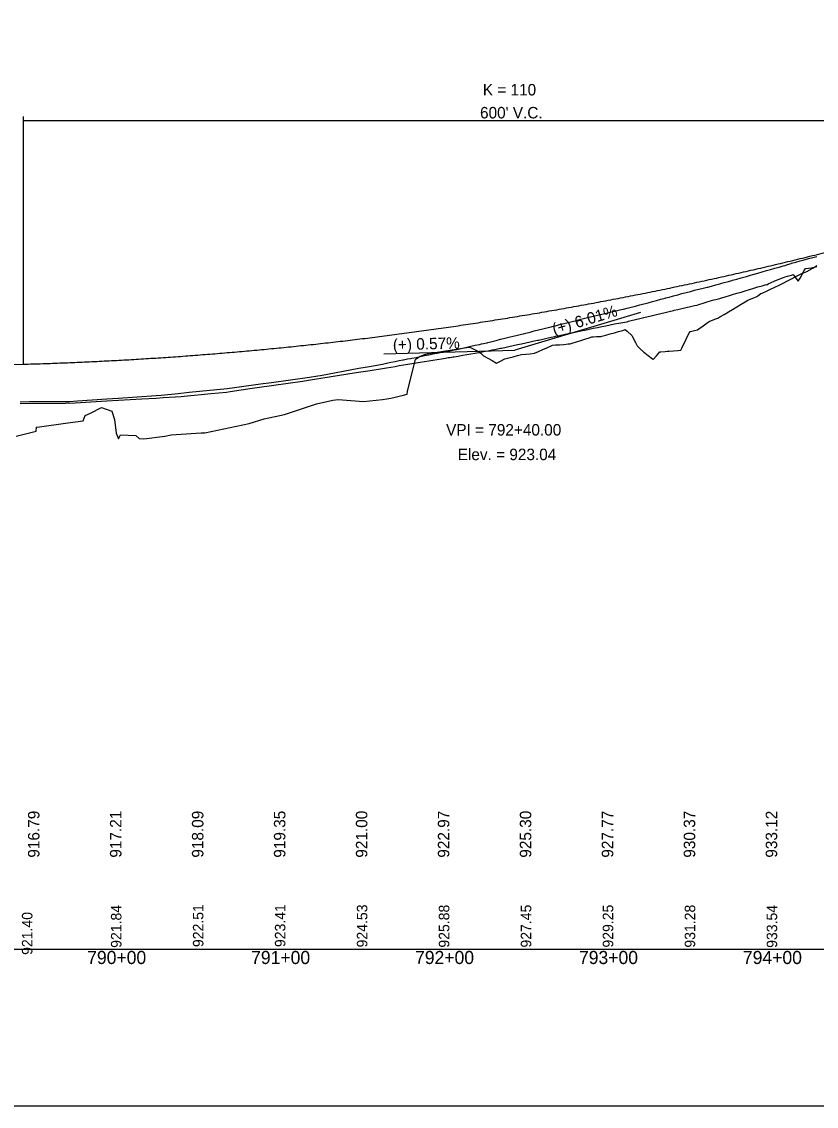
# Model space of a CAD drawing. Extents: x 1558113 to 1562835, y 1129435 to 1135883.
# Drawn here: x 1560436 to 1560920, y 1133348 to 1134009 of the extents above; entities that cross this region are included whole.
import ezdxf

# ---------------------------------------------------------------- set-up
doc = ezdxf.new("R2010")
doc.units = 0
for name, color, linetype in [('BR_EXIST_GROUND_LT', 7, 'Continuous'), ('BR_EXIST_GROUND_RT', 7, 'Continuous'), ('RD_DDB_GradeTX', 7, 'Continuous'), ('RD_DDB_Profile_EX', 7, 'Continuous'), ('RD_DDB_Profile_Lbl', 7, 'Continuous'), ('RD_DDB_Profile_PR', 7, 'Continuous'), ('RD_DDB_StaTX', 7, 'Continuous'), ('RD_DDB_StripGrade', 7, 'Continuous'), ('RD_DDB_VCLbl', 7, 'Continuous'), ('RD_GPK_Profile_Cell', 7, 'Continuous'), ('RD_SHT_ShtClip', 7, 'Continuous')]:
    doc.layers.add(name, color=color, linetype=linetype)

msp = doc.modelspace()

# ---------------------------------------------------------------- linework, layer by layer
at = {"layer": 'BR_EXIST_GROUND_LT'}
msp.add_lwpolyline([(1560432.22, 1133756.64), (1560444.39, 1133759.72), (1560444.6, 1133762.19), (1560444.93, 1133762.16), (1560463.73, 1133764.8), (1560473.02, 1133765.97), (1560474.21, 1133769.22), (1560477.53, 1133770.62), (1560484.26, 1133774.04), (1560490.55, 1133771.91), (1560492.06, 1133766.88), (1560493.06, 1133758.51), (1560494.52, 1133754.99), (1560495.76, 1133757.46), (1560505.12, 1133757.14), (1560507.15, 1133755.18), (1560510.04, 1133755.02), (1560522.83, 1133756.74), (1560526.72, 1133757.57), (1560545.07, 1133758.64), (1560545.49, 1133758.7), (1560547.25, 1133758.76), (1560574.36, 1133764.45), (1560583.49, 1133767.31), (1560595.83, 1133769.83), (1560615.41, 1133776.42), (1560625.36, 1133778.7), (1560628.57, 1133779.09), (1560644.1, 1133777.88), (1560655.52, 1133779.07), (1560658.33, 1133779.39), (1560660.67, 1133779.87), (1560663.24, 1133780.44), (1560665.82, 1133781.05), (1560668.39, 1133781.7), (1560670.57, 1133782.3), (1560670.96, 1133783.91), (1560673.54, 1133794.59), (1560675.65, 1133803.39), (1560676.11, 1133803.72), (1560678.69, 1133805.48), (1560679.45, 1133805.72), (1560681.26, 1133806.35), (1560682.79, 1133806.88), (1560683.83, 1133807.07), (1560686.41, 1133807.48), (1560688.98, 1133807.89), (1560691.56, 1133808.29), (1560694.13, 1133808.7), (1560696.7, 1133809.1), (1560699.28, 1133809.51), (1560701.85, 1133809.91), (1560704.43, 1133810.32), (1560707, 1133810.73), (1560708.75, 1133811), (1560709.62, 1133810.59), (1560712.15, 1133809.33), (1560714.67, 1133808.08), (1560715.45, 1133807.48), (1560717.3, 1133805.72), (1560719.87, 1133804.25), (1560722.45, 1133802.78), (1560725.23, 1133801.22), (1560727.59, 1133802.45), (1560730.17, 1133803.79), (1560732.74, 1133804.45), (1560735.32, 1133805.11), (1560737.89, 1133805.79), (1560740.46, 1133806.44), (1560743.04, 1133806.69), (1560745.61, 1133806.95), (1560748.24, 1133807.22), (1560750.76, 1133808.31), (1560753.33, 1133809.43), (1560755.91, 1133810.57), (1560758.48, 1133811.71), (1560759.39, 1133812.12), (1560761.06, 1133812.24), (1560763.63, 1133812.44), (1560766.2, 1133812.64), (1560768.78, 1133812.87), (1560770.13, 1133812.99), (1560771.35, 1133813.35), (1560773.93, 1133814.14), (1560776.5, 1133814.94), (1560779.07, 1133815.75), (1560781.65, 1133816.58), (1560783.32, 1133817.12), (1560784.22, 1133817.23), (1560786.22, 1133817.47), (1560786.8, 1133817.46), (1560788.7, 1133817.43), (1560789.37, 1133817.61), (1560791.94, 1133818.29), (1560794.52, 1133818.99), (1560797.09, 1133819.7), (1560799.67, 1133820.44), (1560802.24, 1133821.18), (1560803.72, 1133821.62), (1560804.81, 1133820.63), (1560807.64, 1133818.12), (1560809.96, 1133813.7), (1560811.02, 1133811.7), (1560812.54, 1133810.02), (1560815.11, 1133807.9), (1560817.68, 1133805.81), (1560820.26, 1133803.75), (1560820.79, 1133803.34), (1560822.83, 1133805.73), (1560824.77, 1133808.04), (1560825.41, 1133808.08), (1560827.98, 1133808.29), (1560829.28, 1133808.41), (1560830.55, 1133808.48), (1560833.13, 1133808.65), (1560835.7, 1133808.85), (1560837.61, 1133809.03), (1560838.28, 1133810.4), (1560840.85, 1133815.72), (1560843.08, 1133820.37), (1560843.42, 1133820.44), (1560846, 1133821.05), (1560847.81, 1133821.49), (1560848.57, 1133822.03), (1560851.15, 1133823.89), (1560853.72, 1133825.77), (1560854.83, 1133826.58), (1560856.3, 1133827.14), (1560858.87, 1133828.14), (1560860.1, 1133828.62), (1560861.44, 1133829.39), (1560864.02, 1133830.88), (1560866.59, 1133832.39), (1560869.17, 1133833.92), (1560871.74, 1133835.47), (1560874.31, 1133837.04), (1560876.89, 1133838.64), (1560878.5, 1133839.65), (1560879.46, 1133840.02), (1560882.04, 1133841.03), (1560883.87, 1133841.78), (1560884.61, 1133842.28), (1560886.49, 1133843.57), (1560887.18, 1133843.89), (1560889.76, 1133845.07), (1560892.33, 1133846.28), (1560894.91, 1133847.51), (1560897.48, 1133848.76), (1560900.05, 1133850.03), (1560902.63, 1133851.33), (1560905.2, 1133852.65), (1560907.78, 1133853.99), (1560910.61, 1133855.49), (1560912.92, 1133856.46), (1560915.02, 1133857.35), (1560915.5, 1133857.62), (1560918.07, 1133859.11), (1560920.65, 1133860.63)], dxfattribs=at)
at = {"layer": 'BR_EXIST_GROUND_RT'}
msp.add_lwpolyline([(1560434.56, 1133776.53), (1560462.28, 1133776.75), (1560463.96, 1133776.88), (1560464.87, 1133776.85), (1560487.39, 1133778.29), (1560508.75, 1133779.37), (1560517.64, 1133779.81), (1560521.77, 1133780.2), (1560532.83, 1133780.77), (1560534.58, 1133781), (1560551.06, 1133782.57), (1560560.38, 1133783.54), (1560562.72, 1133783.9), (1560576.19, 1133785.83), (1560586.52, 1133787.38), (1560589.32, 1133787.77), (1560606.82, 1133790.27), (1560611.65, 1133791.1), (1560615.42, 1133791.69), (1560618.05, 1133792.07), (1560639.5, 1133795.38), (1560648.01, 1133796.64), (1560655.52, 1133797.94), (1560658.09, 1133798.37), (1560660.67, 1133798.8), (1560663.24, 1133799.23), (1560665.82, 1133799.66), (1560668.39, 1133800.09), (1560671.15, 1133800.55), (1560673.54, 1133800.93), (1560676.11, 1133801.35), (1560678.69, 1133801.77), (1560681.26, 1133802.19), (1560683.83, 1133802.61), (1560686.41, 1133803.03), (1560688.98, 1133803.44), (1560691.56, 1133803.85), (1560694.13, 1133804.26), (1560695.76, 1133804.52), (1560696.7, 1133804.66), (1560698.8, 1133804.98), (1560699.28, 1133805.06), (1560701.85, 1133805.5), (1560704.43, 1133805.94), (1560707, 1133806.38), (1560709.58, 1133806.82), (1560712.15, 1133807.25), (1560713.09, 1133807.4), (1560714.72, 1133807.73), (1560717.3, 1133808.23), (1560719.87, 1133808.73), (1560722.45, 1133809.23), (1560723, 1133809.34), (1560725.02, 1133809.74), (1560727.59, 1133810.25), (1560728.2, 1133810.37), (1560730.17, 1133810.8), (1560732.74, 1133811.37), (1560735.32, 1133811.93), (1560737.89, 1133812.49), (1560740.46, 1133813.04), (1560743.04, 1133813.59), (1560745.61, 1133814.14), (1560746.48, 1133814.32), (1560748.19, 1133814.69), (1560750.29, 1133815.14), (1560750.76, 1133815.25), (1560753.33, 1133815.83), (1560755.91, 1133816.4), (1560758.48, 1133816.97), (1560760.7, 1133817.46), (1560761.06, 1133817.53), (1560763.63, 1133818.09), (1560766.2, 1133818.65), (1560768.78, 1133819.2), (1560771.35, 1133819.75), (1560773.93, 1133820.29), (1560776.5, 1133820.83), (1560777.57, 1133821.05), (1560779.07, 1133821.37), (1560781.65, 1133821.91), (1560784.22, 1133822.44), (1560786.8, 1133822.97), (1560789.37, 1133823.5), (1560791.94, 1133824.02), (1560794.52, 1133824.54), (1560797.09, 1133825.06), (1560799.76, 1133825.59), (1560802.24, 1133825.94), (1560803.49, 1133826.11), (1560804.81, 1133826.46), (1560805.62, 1133826.67), (1560807.39, 1133827.11), (1560809.96, 1133827.76), (1560812.54, 1133828.4), (1560815.11, 1133829.03), (1560817.68, 1133829.66), (1560820.26, 1133830.28), (1560822.83, 1133830.9), (1560825.47, 1133831.52), (1560827.98, 1133832.13), (1560830.55, 1133832.74), (1560833.13, 1133833.35), (1560833.57, 1133833.45), (1560835.7, 1133833.94), (1560838.28, 1133834.53), (1560840.85, 1133835.11), (1560843.42, 1133835.68), (1560846, 1133836.25), (1560847.66, 1133836.61), (1560848.57, 1133836.9), (1560851.15, 1133837.69), (1560853.72, 1133838.48), (1560856.3, 1133839.27), (1560857.77, 1133839.72), (1560858.87, 1133840), (1560861.44, 1133840.66), (1560861.83, 1133840.76), (1560864.02, 1133841.41), (1560865.31, 1133841.79), (1560866.59, 1133842.18), (1560869.17, 1133842.97), (1560871.74, 1133843.75), (1560874.31, 1133844.53), (1560876.89, 1133845.31), (1560879.46, 1133846.09), (1560882.04, 1133846.87), (1560884.61, 1133847.64), (1560887.18, 1133848.41), (1560889.56, 1133849.11), (1560890.03, 1133848.92), (1560890.97, 1133849.58), (1560892.33, 1133850.16), (1560894.91, 1133851.26), (1560897.48, 1133852.36), (1560898.99, 1133853), (1560900.16, 1133853.42), (1560901.29, 1133853.82), (1560902.63, 1133854.19), (1560905.2, 1133854.9), (1560906.14, 1133855.15), (1560907.78, 1133853.08), (1560909.27, 1133851.17), (1560910.35, 1133853.07), (1560912.92, 1133857.59), (1560913.6, 1133858.79), (1560915.5, 1133859.06), (1560917.59, 1133859.35), (1560918.07, 1133859.47), (1560920.65, 1133860.09)], dxfattribs=at)
at = {"layer": 'RD_DDB_GradeTX'}
for p in [(1560812.99, 1133832.04), (1560656.4, 1133806.76)]:
    msp.add_line(p, (1560736.37, 1133809.03), dxfattribs=at)
at = {"layer": 'RD_DDB_Profile_EX'}
msp.add_lwpolyline([(1560434.55, 1133777.69), (1560440.23, 1133777.74), (1560464.55, 1133777.87), (1560469.6, 1133778.15), (1560487.53, 1133779.39), (1560494.28, 1133779.76), (1560517.53, 1133781.38), (1560520.57, 1133781.7), (1560530.96, 1133782.74), (1560537.61, 1133783.45), (1560560.95, 1133785.76), (1560565.39, 1133786.39), (1560581.14, 1133788.48), (1560587.83, 1133789.43), (1560611.13, 1133792.53), (1560616.23, 1133793.47), (1560617.76, 1133793.71), (1560641.19, 1133798.02), (1560647.74, 1133799.08), (1560655.52, 1133800.65), (1560658.09, 1133801.17), (1560660.67, 1133801.68), (1560663.24, 1133802.2), (1560665.82, 1133802.72), (1560667.98, 1133803.15), (1560668.39, 1133803.23), (1560670.96, 1133803.72), (1560672.74, 1133804.05), (1560673.54, 1133804.21), (1560676.11, 1133804.72), (1560678.69, 1133805.24), (1560681.26, 1133805.75), (1560683.83, 1133806.27), (1560686.41, 1133806.78), (1560688.98, 1133807.29), (1560691.56, 1133807.81), (1560692.34, 1133807.96), (1560694.13, 1133808.29), (1560696.7, 1133808.77), (1560697.8, 1133808.97), (1560699.28, 1133809.26), (1560700.8, 1133809.55), (1560701.85, 1133809.78), (1560704.43, 1133810.36), (1560707, 1133810.93), (1560709.58, 1133811.5), (1560712.15, 1133812.07), (1560714.72, 1133812.64), (1560715.93, 1133812.91), (1560717.3, 1133813.19), (1560719.55, 1133813.65), (1560719.87, 1133813.74), (1560722.45, 1133814.4), (1560725.02, 1133815.05), (1560727.59, 1133815.71), (1560730.17, 1133816.36), (1560732.74, 1133817.01), (1560733.57, 1133817.22), (1560735.32, 1133817.63), (1560737.89, 1133818.22), (1560740.46, 1133818.81), (1560741.58, 1133819.07), (1560743.04, 1133819.45), (1560745.61, 1133820.12), (1560748.19, 1133820.79), (1560750.78, 1133821.46), (1560753.33, 1133822.09), (1560755.91, 1133822.72), (1560758.48, 1133823.36), (1560759.2, 1133823.54), (1560761.06, 1133824.01), (1560763.63, 1133824.66), (1560766.2, 1133825.31), (1560768.78, 1133825.96), (1560771.35, 1133826.6), (1560773.93, 1133827.24), (1560776.68, 1133827.93), (1560779.07, 1133828.52), (1560781.65, 1133829.16), (1560784.22, 1133829.79), (1560786.8, 1133830.42), (1560789.37, 1133831.05), (1560791.97, 1133831.68), (1560794.52, 1133832.27), (1560797.09, 1133832.87), (1560799.67, 1133833.46), (1560802.24, 1133834.05), (1560802.62, 1133834.14), (1560804.81, 1133834.7), (1560807.39, 1133835.35), (1560809.96, 1133836), (1560812.54, 1133836.65), (1560815.11, 1133837.29), (1560815.97, 1133837.51), (1560817.68, 1133837.98), (1560820.26, 1133838.68), (1560822.83, 1133839.39), (1560825.41, 1133840.09), (1560827.98, 1133840.79), (1560828.42, 1133840.91), (1560830.55, 1133841.48), (1560833.13, 1133842.18), (1560835.7, 1133842.87), (1560838.28, 1133843.57), (1560840.85, 1133844.25), (1560843.42, 1133844.94), (1560844.1, 1133845.12), (1560846, 1133845.59), (1560848.57, 1133846.22), (1560851.15, 1133846.84), (1560853.72, 1133847.47), (1560854.14, 1133847.57), (1560856.3, 1133848.16), (1560858.87, 1133848.86), (1560861.44, 1133849.57), (1560862.65, 1133849.89), (1560864.02, 1133850.25), (1560865.9, 1133850.74), (1560866.59, 1133850.93), (1560868.79, 1133851.56), (1560869.17, 1133851.67), (1560871.74, 1133852.39), (1560874.31, 1133853.11), (1560876.89, 1133853.83), (1560877.65, 1133854.04), (1560879.46, 1133854.59), (1560882.04, 1133855.36), (1560882.35, 1133855.45), (1560884.61, 1133856.1), (1560887.18, 1133856.83), (1560889.76, 1133857.56), (1560892.33, 1133858.28), (1560894.91, 1133859.01), (1560897.48, 1133859.73), (1560900.05, 1133860.45), (1560901.2, 1133860.77), (1560902.63, 1133861.22), (1560904.88, 1133861.94), (1560905.2, 1133862.03), (1560907.78, 1133862.75), (1560910.35, 1133863.46), (1560912.92, 1133864.17), (1560915.5, 1133864.88), (1560918.07, 1133865.59), (1560920.65, 1133866.29)], dxfattribs=at)
at = {"layer": 'RD_DDB_Profile_PR'}
msp.add_line((1560301.37, 1133796.69), (1560436.37, 1133800.52), dxfattribs=at)
msp.add_spline([(1560436.37, 1133800.52), (1560448.37, 1133800.9), (1560460.37, 1133801.33), (1560472.37, 1133801.84), (1560484.37, 1133802.41), (1560496.37, 1133803.04), (1560508.37, 1133803.74), (1560520.37, 1133804.5), (1560532.37, 1133805.33), (1560544.37, 1133806.23), (1560556.37, 1133807.19), (1560568.37, 1133808.22), (1560580.37, 1133809.31), (1560592.37, 1133810.46), (1560604.37, 1133811.68), (1560616.37, 1133812.97), (1560628.37, 1133814.32), (1560640.37, 1133815.74), (1560652.37, 1133817.22), (1560664.37, 1133818.77), (1560676.37, 1133820.38), (1560688.37, 1133822.06), (1560700.37, 1133823.8), (1560712.37, 1133825.61), (1560724.37, 1133827.49), (1560736.37, 1133829.43), (1560748.37, 1133831.43), (1560760.37, 1133833.5), (1560772.37, 1133835.64), (1560784.37, 1133837.84), (1560796.37, 1133840.1), (1560808.37, 1133842.43), (1560820.37, 1133844.83), (1560832.37, 1133847.29), (1560844.37, 1133849.82), (1560856.37, 1133852.41), (1560868.37, 1133855.07), (1560880.37, 1133857.79), (1560892.37, 1133860.58), (1560904.37, 1133863.43), (1560916.37, 1133866.35), (1560928.37, 1133869.33), (1560940.37, 1133872.38), (1560952.37, 1133875.5), (1560964.37, 1133878.67), (1560976.37, 1133881.92), (1560988.37, 1133885.23), (1561000.37, 1133888.6), (1561012.37, 1133892.04), (1561024.37, 1133895.55), (1561036.37, 1133899.12)], degree=3, dxfattribs=at)
at = {"layer": 'RD_DDB_VCLbl'}
for p, q in [((1560436.37, 1133951.62), (1560436.37, 1133800.52)), ((1560436.37, 1133949.12), (1561036.37, 1133949.12))]:
    msp.add_line(p, q, dxfattribs=at)
at = {"layer": 'RD_GPK_Profile_Cell'}
msp.add_line((1558196.37, 1133443.84), (1562834.74, 1133443.84), dxfattribs=at)
at = {"layer": 'RD_SHT_ShtClip'}
msp.add_lwpolyline([(1559525.21, 1134448.11), (1561325.21, 1134448.11), (1561325.21, 1133348.11), (1559525.21, 1133348.11)], close=True, dxfattribs=at)

# ---------------------------------------------------------------- texts
at = {"layer": 'RD_DDB_GradeTX'}
for s, rotation, p in [('(+) 6.01%', 16.71501, (1560760.38, 1133818.33)), ('(+) 0.57%', 1.62458, (1560662.01, 1133808.92))]:
    msp.add_text(s, height=7, rotation=rotation, dxfattribs=at).set_placement(p)
at = {"layer": 'RD_DDB_Profile_Lbl'}
for s, p in [('VPI = 792+40.00', (1560694.4, 1133757.03)), ('Elev. = 923.04', (1560701.51, 1133742.03))]:
    msp.add_text(s, height=7, dxfattribs=at).set_placement(p)
at = {"layer": 'RD_DDB_StaTX'}
for s, p in [('790+00', (1560475.47, 1133434.84)), ('791+00', (1560575.47, 1133434.84)), ('792+00', (1560675.47, 1133434.84)), ('793+00', (1560775.47, 1133434.84)), ('794+00', (1560875.47, 1133434.84))]:
    msp.add_text(s, height=8, dxfattribs=at).set_placement(p)
at = {"layer": 'RD_DDB_StripGrade'}
for s, height, p in [('916.79', 7, (1560446.37, 1133499.68)), ('917.21', 7, (1560496.37, 1133499.68)), ('918.09', 7, (1560546.37, 1133499.68)), ('919.35', 7, (1560596.37, 1133499.68)), ('921.00', 7, (1560646.37, 1133499.68)), ('922.97', 7, (1560696.37, 1133499.68)), ('925.30', 7, (1560746.37, 1133499.68)), ('927.77', 7, (1560796.37, 1133499.68)), ('930.37', 7, (1560846.37, 1133499.68)), ('933.12', 7, (1560896.37, 1133499.68)), ('921.84', 6.4, (1560496.37, 1133444.71)), ('922.51', 6.4, (1560546.37, 1133445.18)), ('923.41', 6.4, (1560596.37, 1133445.18)), ('924.53', 6.4, (1560646.37, 1133444.97)), ('925.88', 6.4, (1560696.37, 1133444.84)), ('927.45', 6.4, (1560746.37, 1133444.88)), ('929.25', 6.4, (1560796.37, 1133444.88)), ('931.28', 6.4, (1560846.37, 1133444.84)), ('933.54', 6.4, (1560896.37, 1133444.71)), ('921.40', 6.4, (1560442.06, 1133440.41))]:
    msp.add_text(s, height=height, rotation=90, dxfattribs=at).set_placement(p)
at = {"layer": 'RD_DDB_VCLbl'}
for s, p in [('K = 110', (1560716.81, 1133964.37)), ("600' V.C.", (1560715.11, 1133950.37))]:
    msp.add_text(s, height=7, dxfattribs=at).set_placement(p)

doc.saveas('drawing.dxf')
